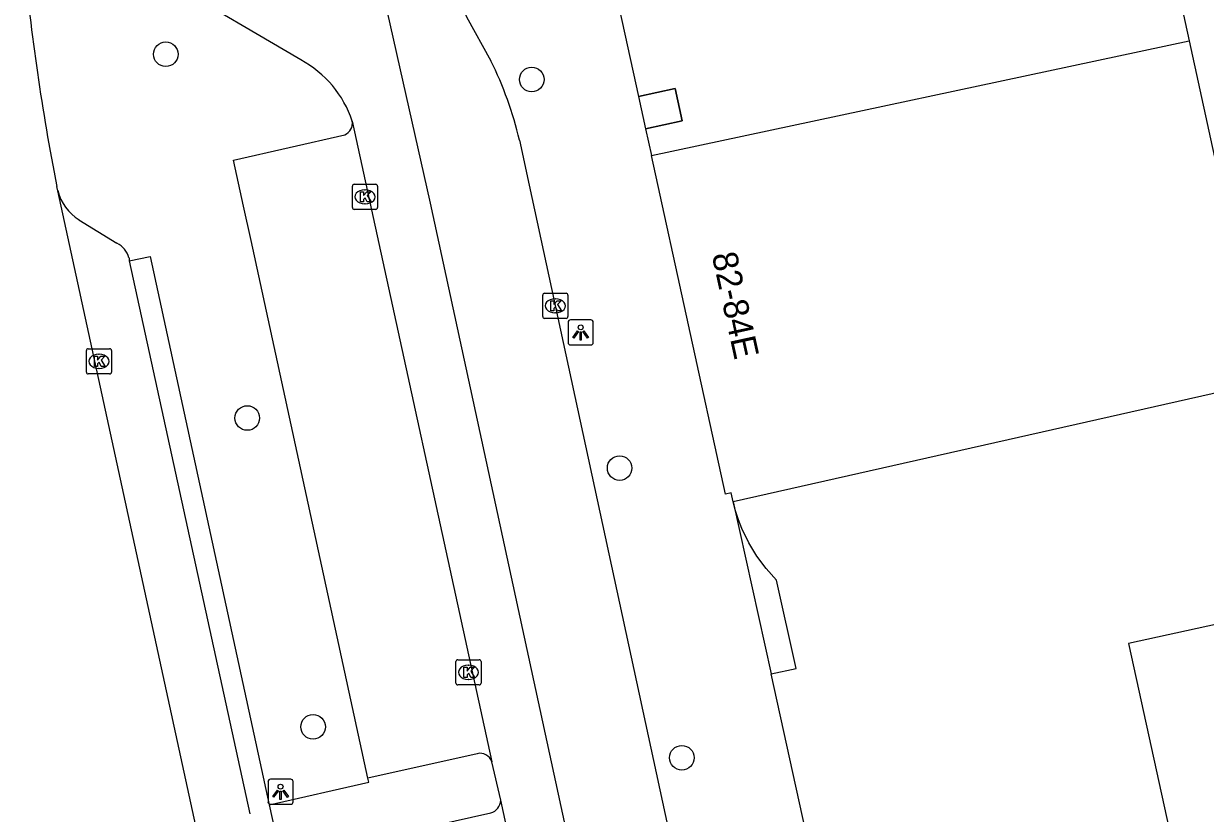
# Model space of a CAD drawing. Extents: x 160557 to 161245, y 385330 to 386505.
# Drawn here: x 160733.46 to 160780.49, y 385828.37 to 385859.79 of the extents above; entities that cross this region are included whole.
import ezdxf

# ---------------------------------------------------------------- set-up
doc = ezdxf.new("R2010")
doc.units = 0
for name, color, linetype in [('IMGEO_Boom', 7, 'Continuous'), ('IMGEO_Fietspad_gesloten', 7, 'Continuous'), ('IMGEO_Kolk', 7, 'Continuous'), ('IMGEO_Lichtpunt', 7, 'Continuous'), ('IMGEO_Pand', 7, 'Continuous'), ('IMGEO_Pand_nummerreeks', 7, 'Continuous'), ('IMGEO_Pand_overbouw', 7, 'Continuous'), ('IMGEO_Parkeervlak_open', 7, 'Continuous'), ('IMGEO_Rijbaan_lokaal_gesloten', 7, 'Continuous'), ('IMGEO_Voetpad_open', 7, 'Continuous')]:
    doc.layers.add(name, color=color, linetype=linetype)

msp = doc.modelspace()

# ---------------------------------------------------------------- linework, layer by layer
at = {"layer": 'IMGEO_Boom'}
for centre in [(160739.118, 385858.569), (160753.68, 385857.563), (160742.358, 385844.098), (160757.177, 385842.106), (160744.979, 385831.813), (160759.653, 385830.583)]:
    msp.add_circle(centre, 0.489, dxfattribs=at)
at = {"layer": 'IMGEO_Fietspad_gesloten'}
for points in [[(160747.348, 385875.432), (160750.213, 385862.278), (160751.082, 385860.062), (160752.047, 385858.308)], [(160775.118, 385735.103), (160749.654, 385852.647), (160746.978, 385864.559), (160746.687, 385864.512)], [(160753.194, 385855.146), (160753.582, 385853.359), (160768.677, 385783.529), (160779.078, 385735.819)]]:
    msp.add_lwpolyline(points, dxfattribs=at)
msp.add_arc((160739.597, 385852.003), 13.955, 13.0162, 26.8598, dxfattribs=at)
at = {"layer": 'IMGEO_Kolk'}
for p, q in [((160746.543, 385852.469), (160746.543, 385853.321)), ((160746.618, 385853.395), (160747.47, 385853.395)), ((160747.031, 385853.175), (160747.056, 385853.175)), ((160747.544, 385853.321), (160747.544, 385852.469)), ((160747.054, 385852.615), (160747.029, 385852.615)), ((160747.47, 385852.395), (160746.618, 385852.395)), ((160754.118, 385848.135), (160754.118, 385848.987)), ((160754.193, 385849.061), (160755.045, 385849.061)), ((160755.119, 385848.987), (160755.119, 385848.135)), ((160754.606, 385848.841), (160754.631, 385848.841)), ((160755.045, 385848.061), (160754.193, 385848.061)), ((160754.629, 385848.281), (160754.604, 385848.281)), ((160735.957, 385845.927), (160735.957, 385846.779)), ((160736.032, 385846.853), (160736.884, 385846.853)), ((160736.445, 385846.633), (160736.47, 385846.633)), ((160736.958, 385846.779), (160736.958, 385845.927)), ((160736.468, 385846.073), (160736.443, 385846.073)), ((160736.884, 385845.853), (160736.032, 385845.853)), ((160750.662, 385833.555), (160750.662, 385834.407)), ((160750.737, 385834.481), (160751.589, 385834.481)), ((160751.663, 385834.407), (160751.663, 385833.555)), ((160751.15, 385834.261), (160751.175, 385834.261)), ((160751.589, 385833.481), (160750.737, 385833.481)), ((160751.173, 385833.701), (160751.148, 385833.701))]:
    msp.add_line(p, q, dxfattribs=at)
for points in [[(160746.543, 385852.469), (160746.543, 385853.321)], [(160746.618, 385853.395), (160747.47, 385853.395)], [(160746.864, 385853.095), (160746.987, 385853.095), (160746.987, 385852.944), (160747.117, 385853.095), (160747.281, 385853.095), (160747.135, 385852.944), (160747.288, 385852.695), (160747.136, 385852.695), (160747.051, 385852.859), (160746.987, 385852.792), (160746.987, 385852.695), (160746.864, 385852.695), (160746.864, 385853.095)], [(160747.544, 385853.321), (160747.544, 385852.469)], [(160747.47, 385852.395), (160746.618, 385852.395)], [(160754.118, 385848.135), (160754.118, 385848.987)], [(160754.193, 385849.061), (160755.045, 385849.061)], [(160755.119, 385848.987), (160755.119, 385848.135)], [(160754.439, 385848.761), (160754.562, 385848.761), (160754.562, 385848.61), (160754.692, 385848.761), (160754.856, 385848.761), (160754.71, 385848.61), (160754.863, 385848.361), (160754.711, 385848.361), (160754.626, 385848.525), (160754.562, 385848.458), (160754.562, 385848.361), (160754.439, 385848.361), (160754.439, 385848.761)], [(160755.045, 385848.061), (160754.193, 385848.061)], [(160735.957, 385845.927), (160735.957, 385846.779)], [(160736.032, 385846.853), (160736.884, 385846.853)], [(160736.278, 385846.553), (160736.401, 385846.553), (160736.401, 385846.402), (160736.531, 385846.553), (160736.695, 385846.553), (160736.549, 385846.402), (160736.702, 385846.153), (160736.55, 385846.153), (160736.465, 385846.317), (160736.401, 385846.25), (160736.401, 385846.153), (160736.278, 385846.153), (160736.278, 385846.553)], [(160736.958, 385846.779), (160736.958, 385845.927)], [(160736.884, 385845.853), (160736.032, 385845.853)], [(160750.662, 385833.555), (160750.662, 385834.407)], [(160750.737, 385834.481), (160751.589, 385834.481)], [(160751.663, 385834.407), (160751.663, 385833.555)], [(160750.983, 385834.181), (160751.106, 385834.181), (160751.106, 385834.03), (160751.236, 385834.181), (160751.4, 385834.181), (160751.254, 385834.03), (160751.407, 385833.781), (160751.255, 385833.781), (160751.17, 385833.945), (160751.106, 385833.878), (160751.106, 385833.781), (160750.983, 385833.781), (160750.983, 385834.181)], [(160751.589, 385833.481), (160750.737, 385833.481)]]:
    msp.add_lwpolyline(points, dxfattribs=at)
for centre, start, end in [((160746.62, 385853.319), 91.552, 178.448), ((160746.62, 385853.319), 91.552, 178.448), ((160747.468, 385853.319), 1.552, 88.448), ((160747.468, 385853.319), 1.552, 88.448), ((160746.62, 385852.471), 181.552, 268.448), ((160746.62, 385852.471), 181.552, 268.448), ((160747.468, 385852.471), 271.552, 358.448), ((160747.468, 385852.471), 271.552, 358.448), ((160754.195, 385848.985), 91.552, 178.448), ((160754.195, 385848.985), 91.552, 178.448), ((160755.043, 385848.985), 1.552, 88.448), ((160755.043, 385848.985), 1.552, 88.448), ((160754.195, 385848.137), 181.552, 268.448), ((160754.195, 385848.137), 181.552, 268.448), ((160755.043, 385848.137), 271.552, 358.448), ((160755.043, 385848.137), 271.552, 358.448), ((160736.034, 385846.777), 91.552, 178.448), ((160736.034, 385846.777), 91.552, 178.448), ((160736.882, 385846.777), 1.552, 88.448), ((160736.882, 385846.777), 1.552, 88.448), ((160736.034, 385845.929), 181.552, 268.448), ((160736.034, 385845.929), 181.552, 268.448), ((160736.882, 385845.929), 271.552, 358.448), ((160736.882, 385845.929), 271.552, 358.448), ((160750.739, 385834.405), 91.552, 178.448), ((160750.739, 385834.405), 91.552, 178.448), ((160751.587, 385834.405), 1.552, 88.448), ((160751.587, 385834.405), 1.552, 88.448), ((160750.739, 385833.557), 181.552, 268.448), ((160750.739, 385833.557), 181.552, 268.448), ((160751.587, 385833.557), 271.552, 358.448), ((160751.587, 385833.557), 271.552, 358.448)]:
    msp.add_arc(centre, 0.0765, start, end, dxfattribs=at)
for centre, major_axis, ratio, start_param, end_param in [((160747.03, 385852.895), (-0.387, 0.002), 0.722429, 4.712389, 7.853982), ((160747.055, 385852.895), (-0.39, 0.002), 0.717154, 1.570796, 4.712389), ((160754.605, 385848.561), (-0.387, 0.002), 0.722429, 4.712389, 7.853982), ((160754.63, 385848.561), (-0.39, 0.002), 0.717154, 1.570796, 4.712389), ((160736.444, 385846.353), (-0.387, 0.002), 0.722429, 4.712389, 7.853982), ((160736.469, 385846.353), (-0.39, 0.002), 0.717154, 1.570796, 4.712389), ((160751.149, 385833.981), (-0.387, 0.002), 0.722429, 4.712389, 7.853982), ((160751.174, 385833.981), (-0.39, 0.002), 0.717154, 1.570796, 4.712389)]:
    msp.add_ellipse(centre, major_axis=major_axis, ratio=ratio, start_param=start_param, end_param=end_param, dxfattribs=at)
at = {"layer": 'IMGEO_Lichtpunt'}
for p, q in [((160756.031, 385848.001), (160755.223, 385848.001)), ((160756.031, 385848.001), (160755.223, 385848.001)), ((160755.129, 385847.906), (160755.129, 385847.099)), ((160755.129, 385847.906), (160755.129, 385847.099)), ((160756.125, 385847.099), (160756.125, 385847.906)), ((160756.125, 385847.099), (160756.125, 385847.906)), ((160755.223, 385847.005), (160756.031, 385847.005)), ((160755.223, 385847.005), (160756.031, 385847.005)), ((160743.185, 385829.635), (160743.185, 385828.828)), ((160743.185, 385829.635), (160743.185, 385828.828)), ((160744.087, 385829.73), (160743.279, 385829.73)), ((160744.087, 385829.73), (160743.279, 385829.73)), ((160744.181, 385828.828), (160744.181, 385829.635)), ((160744.181, 385828.828), (160744.181, 385829.635)), ((160743.279, 385828.734), (160744.087, 385828.734)), ((160743.279, 385828.734), (160744.087, 385828.734))]:
    msp.add_line(p, q, dxfattribs=at)
for points in [[(160755.503, 385847.57), (160755.542, 385847.542), (160755.354, 385847.28), (160755.316, 385847.307), (160755.503, 385847.57)], [(160755.605, 385847.522), (160755.652, 385847.522), (160755.652, 385847.2), (160755.605, 385847.2), (160755.605, 385847.522)], [(160755.715, 385847.542), (160755.753, 385847.569), (160755.94, 385847.307), (160755.901, 385847.279), (160755.715, 385847.542)], [(160743.559, 385829.299), (160743.598, 385829.271), (160743.41, 385829.009), (160743.372, 385829.036), (160743.559, 385829.299)], [(160743.661, 385829.251), (160743.708, 385829.251), (160743.708, 385828.929), (160743.661, 385828.929), (160743.661, 385829.251)], [(160743.771, 385829.271), (160743.809, 385829.298), (160743.996, 385829.036), (160743.957, 385829.008), (160743.771, 385829.271)]]:
    msp.add_lwpolyline(points, dxfattribs=at)
for centre in [(160755.628, 385847.704), (160743.684, 385829.433)]:
    msp.add_circle(centre, 0.0994, dxfattribs=at)
for centre, start, end in [((160755.223, 385847.906), 90, 180), ((160755.223, 385847.906), 90, 180), ((160756.031, 385847.906), 0, 90), ((160756.031, 385847.906), 0, 90), ((160755.223, 385847.099), 180, 270), ((160755.223, 385847.099), 180, 270), ((160756.031, 385847.099), 270, 0), ((160756.031, 385847.099), 270, 360), ((160743.279, 385829.635), 90, 180), ((160743.279, 385829.635), 90, 180), ((160744.087, 385829.635), 0, 90), ((160744.087, 385829.635), 0, 90), ((160743.279, 385828.828), 180, 270), ((160743.279, 385828.828), 180, 270), ((160744.087, 385828.828), 270, 0), ((160744.087, 385828.828), 270, 360)]:
    msp.add_arc(centre, 0.0946, start, end, dxfattribs=at)
at = {"layer": 'IMGEO_Pand'}
for points in [[(160777.279, 385870.849), (160779.843, 385859.099)], [(160755.843, 385866.393), (160757.924, 385856.888), (160759.385, 385857.208), (160759.667, 385855.919), (160758.206, 385855.6), (160758.439, 385854.537)], [(160758.439, 385854.537), (160779.843, 385859.099)], [(160779.843, 385859.099), (160781.346, 385852.214), (160785.461, 385853.115), (160785.345, 385853.643), (160788.241, 385854.277), (160789.778, 385847.261)], [(160761.698, 385840.764), (160761.62, 385841.119), (160761.387, 385841.069), (160758.439, 385854.537)], [(160789.778, 385847.261), (160789.816, 385847.106), (160761.698, 385840.764)], [(160763.205, 385833.915), (160764.197, 385834.133), (160763.423, 385837.649), (160763.006, 385838.109), (160762.635, 385838.607), (160762.314, 385839.138), (160762.044, 385839.697), (160761.908, 385840.046), (160761.794, 385840.4), (160761.698, 385840.764)], [(160797.582, 385839.533), (160777.43, 385835.122), (160782.162, 385813.51)], [(160767.998, 385810.411), (160766.088, 385819.108), (160766.446, 385819.186), (160763.205, 385833.915)]]:
    msp.add_lwpolyline(points, dxfattribs=at)
at = {"layer": 'IMGEO_Pand_overbouw'}
for points in [[(160758.206, 385855.6), (160759.667, 385855.919), (160759.385, 385857.208), (160757.924, 385856.888)], [(160763.205, 385833.915), (160764.197, 385834.133), (160763.423, 385837.649), (160763.006, 385838.109), (160762.635, 385838.607), (160762.314, 385839.138), (160762.044, 385839.697), (160761.908, 385840.046), (160761.794, 385840.4), (160761.698, 385840.764)]]:
    msp.add_lwpolyline(points, close=True, dxfattribs=at)
at = {"layer": 'IMGEO_Parkeervlak_open'}
for points in [[(160747.16, 385829.766), (160742.513, 385851.153), (160742.213, 385852.528), (160741.815, 385854.355), (160746.236, 385855.367)], [(160735.664, 385851.975), (160737.173, 385851.055)], [(160737.654, 385850.466), (160737.667, 385850.35)]]:
    msp.add_lwpolyline(points, dxfattribs=at)
for centre, radius, start, end in [((160746.043, 385855.83), 0.502, 292.5904, 8.9055), ((160736.73, 385853.642), 1.978, 194.6575, 237.3972), ((160736.76, 385850.227), 0.925, 14.9657, 63.5071)]:
    msp.add_arc(centre, radius, start, end, dxfattribs=at)
at = {"layer": 'IMGEO_Rijbaan_lokaal_gesloten'}
for points in [[(160734.816, 385853.141), (160734.78, 385853.307)], [(160740.309, 385827.873), (160734.816, 385853.141)]]:
    msp.add_lwpolyline(points, dxfattribs=at)
msp.add_arc((160828.417, 385871.536), 95.395, 185.49799, 191.0163, dxfattribs=at)
at = {"layer": 'IMGEO_Voetpad_open'}
for points in [[(160744.49, 385858.341), (160734.067, 385864.463)], [(160746.539, 385855.908), (160752.087, 385830.426)], [(160737.667, 385850.35), (160738.499, 385850.527), (160743.233, 385828.714)], [(160737.667, 385850.35), (160742.46, 385828.352)], [(160761.698, 385840.764), (160763.205, 385833.915)], [(160751.504, 385830.745), (160747.16, 385829.766)], [(160752.445, 385828.891), (160752.087, 385830.426)], [(160743.233, 385828.714), (160747.193, 385829.613), (160747.16, 385829.766)], [(160743.233, 385828.714), (160743.679, 385826.657)], [(160758.99, 385798.701), (160752.445, 385828.891)], [(160747.68, 385827.413), (160752.051, 385828.391)]]:
    msp.add_lwpolyline(points, dxfattribs=at)
for centre, radius, start, end in [((160742.446, 385854.54), 4.315, 18.4767, 61.7295), ((160751.628, 385830.279), 0.482, 17.7799, 104.8478), ((160751.891, 385828.922), 0.555, 286.7399, 356.7839)]:
    msp.add_arc(centre, radius, start, end, dxfattribs=at)

# ---------------------------------------------------------------- texts
at = {"layer": 'IMGEO_Pand_nummerreeks'}
msp.add_text('82-84E', height=1, rotation=282.347, dxfattribs=at).set_placement((160760.839, 385850.59))

doc.saveas('drawing.dxf')
